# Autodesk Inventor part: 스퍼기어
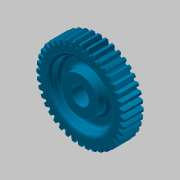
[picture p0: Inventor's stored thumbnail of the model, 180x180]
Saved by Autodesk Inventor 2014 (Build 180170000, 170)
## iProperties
Created: 2018-11
Part Number: 스퍼기어
Material: 알루미늄 6061
Document SubType Name: Modeling
Designer: mduedu
Categories: <?xml version="1.0" encoding="UTF-16"?> <MemberInstance><Categories><FamilyTemplate><FamilyTemplateParameter ValueType="xs:double" Id="1" ObjectReferenceKey="da
Density: 1 g/cm^3
Appearance: 하늘색 중간
CustomPartVersion: 1
Author: mduedu
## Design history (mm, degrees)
sketch "Sketch1"
  geometry: C1 r 42 at (0, 0)
  constraints: 1 centre point
  dimensions: "d0" = 83.99905 diameter of C1 (= da_da)
extrude "Extrusion1" new body sketch "Sketch1" distance "d1" = 19 (= da_b); taper "d2" = 0 deg
workplane "Work Plane2"
sketch "Sketch2"
  geometry: C1 r 42 at (0, 0) reference; C2 r 40.05 at (0, 0)
  constraints: 1 centre point, 1 coincident
  dimensions: "d3" = 80.10038 diameter of C2 (= da_dw)
feature "피치 지름" sketch "Sketch2" dims "d4" = 10, "d5" = 0
workplane "Work Plane8"
workplane "Work Plane9"
feature "스퍼 기어" dims "da_b" = 19, "da_d" = 80, "da_aw" = 80.10038, "da_da" = 83.99905, "da_df" = 75, "da_dw" = 80.10038, angle "da_beta" = 0 deg, "da_lefttooth" = 0, "da_righttooth" = 0
sketch "스케치3"
  geometry: L1 (-42, 19)-(42, 19) reference; L2 (42, 19)-(42, 0) reference; L3 (42, 0)-(-42, 0) reference; L4 (-42, 0)-(-42, 19) reference; L5 (0, 0)-(0, 19); L6 (42, 0)-(41, 0); L7 (42, 1)-(42, 0); L8 (42, 19)-(41, 19); L9 (42, 18)-(42, 19); L10 (41, 19)-(42, 18); L11 (41, 0)-(42, 1)
  constraints: 14 end point, 2 horizontal, 2 vertical, 1 midpoint
  dimensions: "d49" = 1 distance from line of L8.end L2; "d50" = 1 horizontal distance of L8.end L9.start; "d51" = 1 horizontal distance of L6.end L7.start; "d52" = 1 horizontal distance of L6.end L7.start
revolve "회전1" sketch "스케치3" stored, may be unused: angle "d53" = 90 deg
sketch "스케치4"
  geometry: L1 (-2.5, 8.124)-(2.5, 8.124); L2 (2.5, 8.124)-(2.5, 10.8); L3 (2.5, 10.8)-(-2.5, 10.8); L4 (-2.5, 10.8)-(-2.5, 8.124); A1 r 8.5 centre (0, 0) between (-2.5, 8.124) and (2.5, 8.124); 1 further point
  constraints: 8 end point, 2 parallel, 2 point on circle, 1 centre point, 1 coincident, 1 horizontal, 1 perpendicular
  dimensions: "d54" = 17 diameter of A1; "d56" = 19.3 dimension on A1 L3; "d57" = 5 distance of L2.end L3.end
extrude "돌출2" cut sketch "스케치4" stored distance "d58" = 10; taper "d59" = 0 deg
chamfer "모따기1" distance "d60" = 1; stored, may be unused: second distance "d61" = 2, angle "d62" = 45 deg
sketch "스케치5"
  geometry: C1 r 17.5 at (0, 0); C2 r 28.5 at (0, 0); 1 further point
  constraints: 2 centre point, 2 coincident
  dimensions: "d63" = 35 diameter of C1; "d64" = 57 diameter of C2
extrude "돌출3" cut sketch "스케치5" distance "d65" = 9.5; taper "d66" = 0 deg
fillet "모깎기1" dims "d67" = 3
body "Solid1"
body "Srf1"
node "절단 모서리 투영1"
other parameters: "d16" = 80.10038 (= da_aw), "d17" = 0, "d34" = 4.5 deg (computed from da_z), "d39" = 0, "d41" = 0, "d43" = 80.10038 (= da_aw), "d46" = 80.10038 (= da_aw), "d47" = 0, "d48" = 0
